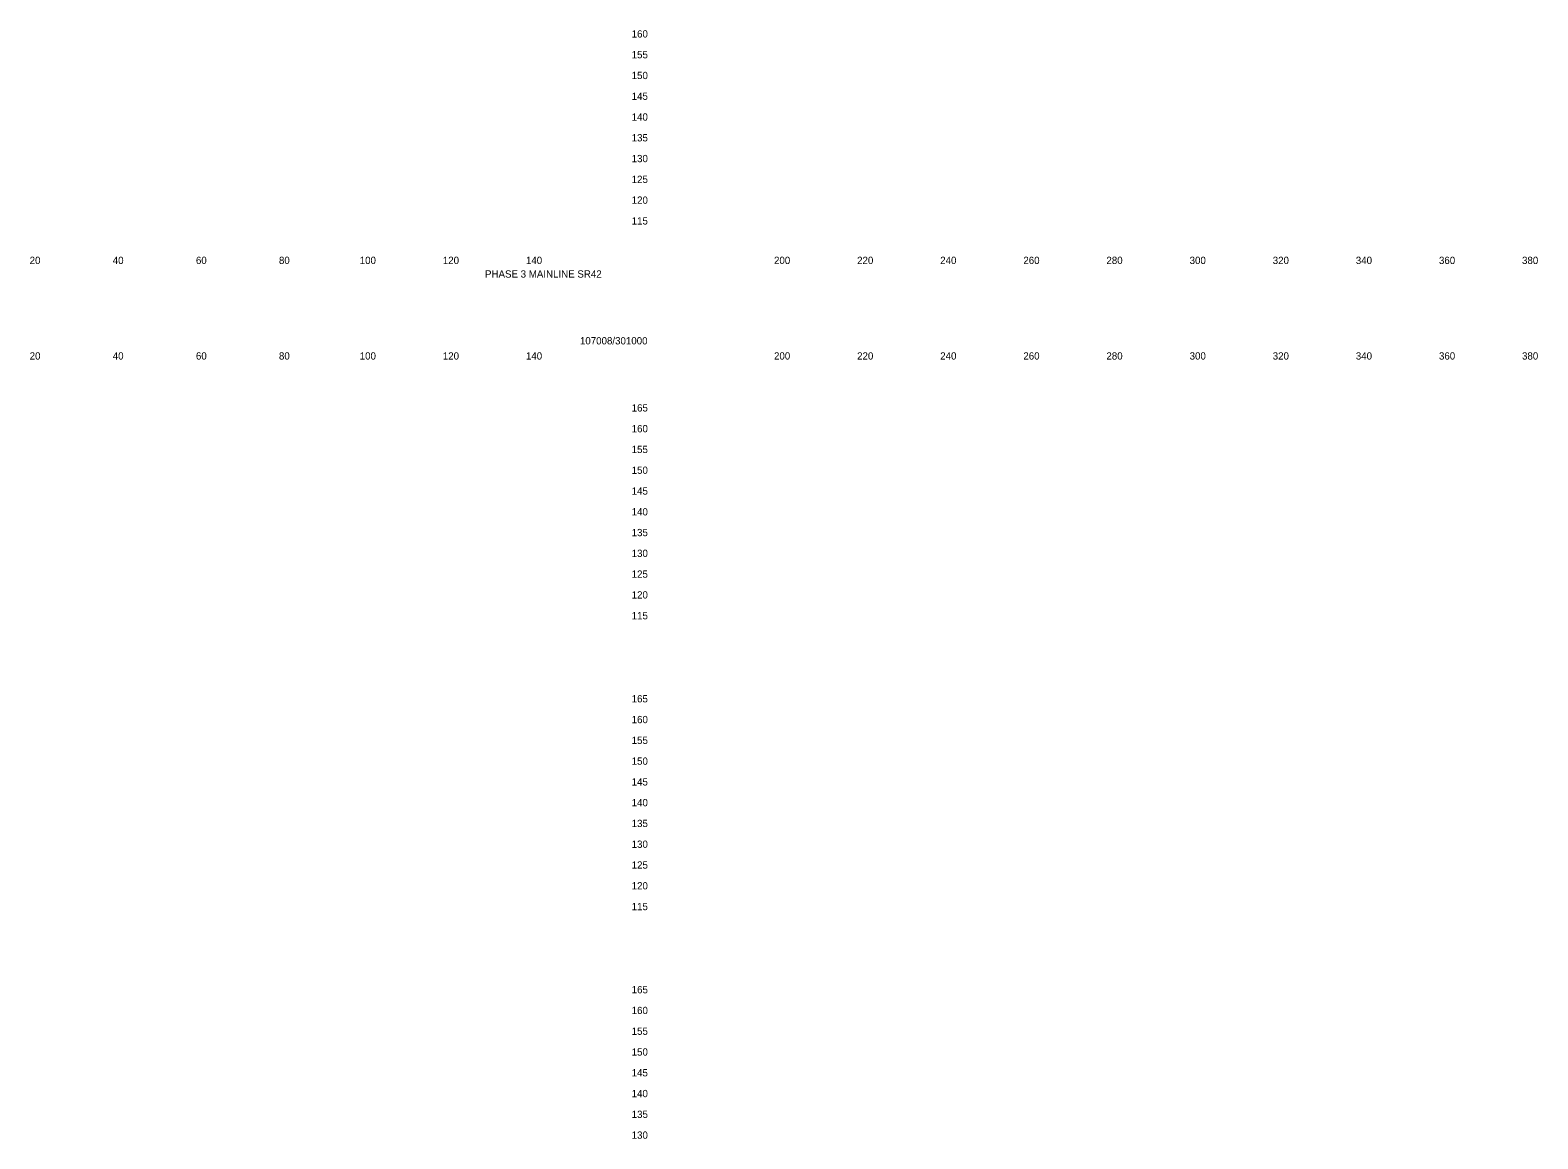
# Model space of a CAD drawing. Extents: x 21281 to 22024, y 6472 to 15198.
# Drawn here: x 21661.4 to 22024.2, y 8104.8 to 8371.6 of the extents above; entities that cross this region are included whole.
import ezdxf

# ---------------------------------------------------------------- set-up
doc = ezdxf.new("R2010")
doc.units = 0
doc.layers.add('Draft_XS_Grid', color=7, linetype='Continuous')
doc.layers.add('Draft_XS_Text', color=7, linetype='Continuous')

msp = doc.modelspace()

# ---------------------------------------------------------------- texts
at = {"layer": 'Draft_XS_Grid'}
for s, p in [('  160  ', (21804.84, 8369.84)), ('  155  ', (21804.84, 8364.84)), ('  150  ', (21804.84, 8359.84)), ('  145  ', (21804.84, 8354.84)), ('  140  ', (21804.84, 8349.84)), ('  135  ', (21804.84, 8344.84)), ('  130  ', (21804.84, 8339.84)), ('  125  ', (21804.84, 8334.84)), ('  120  ', (21804.84, 8329.84)), ('  115  ', (21804.84, 8324.84)), ('  165  ', (21804.84, 8279.84)), ('  160  ', (21804.84, 8274.84)), ('  155  ', (21804.84, 8269.84)), ('  150  ', (21804.84, 8264.84)), ('  145  ', (21804.84, 8259.84)), ('  140  ', (21804.84, 8254.84)), ('  135  ', (21804.84, 8249.84)), ('  130  ', (21804.84, 8244.84)), ('  125  ', (21804.84, 8239.84)), ('  120  ', (21804.84, 8234.84)), ('  115  ', (21804.84, 8229.84)), ('  165  ', (21804.84, 8209.84)), ('  160  ', (21804.84, 8204.84)), ('  155  ', (21804.84, 8199.84)), ('  150  ', (21804.84, 8194.84)), ('  145  ', (21804.84, 8189.84)), ('  140  ', (21804.84, 8184.84)), ('  135  ', (21804.84, 8179.84)), ('  130  ', (21804.84, 8174.84)), ('  125  ', (21804.84, 8169.84)), ('  120  ', (21804.84, 8164.84)), ('  115  ', (21804.84, 8159.84)), ('  165  ', (21804.84, 8139.84)), ('  160  ', (21804.84, 8134.84)), ('  155  ', (21804.84, 8129.84)), ('  150  ', (21804.84, 8124.84)), ('  145  ', (21804.84, 8119.84)), ('  140  ', (21804.84, 8114.84)), ('  135  ', (21804.84, 8109.84)), ('  130  ', (21804.84, 8104.84))]:
    msp.add_text(s, height=1.75, dxfattribs=at).set_placement(p)
at = {"layer": 'Draft_XS_Text'}
for s, p in [('  20  ', (21659.95, 8315.34)), ('  40  ', (21679.95, 8315.34)), ('  60  ', (21699.97, 8315.34)), ('  80  ', (21719.95, 8315.34)), ('  100  ', (21739.39, 8315.34)), ('  120  ', (21759.39, 8315.34)), ('  140  ', (21779.39, 8315.34)), ('  200  ', (21839.1, 8315.34)), ('  220  ', (21859.1, 8315.34)), ('  240  ', (21879.1, 8315.34)), ('  260  ', (21899.11, 8315.34)), ('  280  ', (21919.1, 8315.34)), ('  300  ', (21939.13, 8315.34)), ('  320  ', (21959.13, 8315.34)), ('  340  ', (21979.13, 8315.34)), ('  360  ', (21999.14, 8315.34)), ('  380  ', (22019.13, 8315.34)), ('PHASE 3 MAINLINE SR42', (21770.84, 8312.06)), ('107008/301000', (21793.69, 8295.99)), ('  20  ', (21659.95, 8292.34)), ('  40  ', (21679.95, 8292.34)), ('  60  ', (21699.97, 8292.34)), ('  80  ', (21719.95, 8292.34)), ('  100  ', (21739.39, 8292.34)), ('  120  ', (21759.39, 8292.34)), ('  140  ', (21779.39, 8292.34)), ('  200  ', (21839.1, 8292.34)), ('  220  ', (21859.1, 8292.34)), ('  240  ', (21879.1, 8292.34)), ('  260  ', (21899.11, 8292.34)), ('  280  ', (21919.1, 8292.34)), ('  300  ', (21939.13, 8292.34)), ('  320  ', (21959.13, 8292.34)), ('  340  ', (21979.13, 8292.34)), ('  360  ', (21999.14, 8292.34)), ('  380  ', (22019.13, 8292.34))]:
    msp.add_text(s, height=1.75, dxfattribs=at).set_placement(p)

doc.saveas('drawing.dxf')
